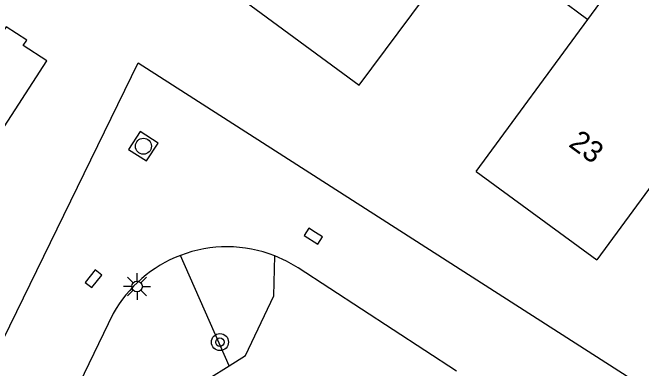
# Model space of a CAD drawing. Extents: x 136000 to 141000, y 400494 to 402006.
# Drawn here: x 137668.02 to 137697.45, y 401848.15 to 401864.81 of the extents above; entities that cross this region are included whole.
import ezdxf

# ---------------------------------------------------------------- set-up
doc = ezdxf.new("R2010")
doc.units = 0
for name, color, linetype in [('gg-anno-huisnummerreeks BGT', 7, 'Continuous'), ('gg-bbg-gedigitaliseerde bebouwing', 7, 'Continuous'), ('gg-bbg-hoofdgebouw', 7, 'Continuous'), ('gg-bbg-luifel en loopbrug', 7, 'Continuous'), ('gg-knt-verharding', 7, 'Continuous'), ('gt-grn-groengrens', 7, 'Continuous'), ('gt-symb-boom', 7, 'Continuous'), ('gt-symb-kolk', 7, 'Continuous'), ('gt-symb-lichtmast', 7, 'Continuous'), ('gt-symb-rioolschacht', 7, 'Continuous')]:
    doc.layers.add(name, color=color, linetype=linetype)

# ---------------------------------------------------------------- blocks, each defined once
blk = doc.blocks.new('gt0-KOLK')
at = {"layer": 'gt-symb-kolk'}
blk.add_lwpolyline([(0, 0), (0.375, 0), (0.375, 0.4), (-0.375, 0.4), (-0.375, 0), (0, 0)], dxfattribs=at)
blk = doc.blocks.new('gt0-BOOM')
at = {"layer": 'gt-symb-boom'}
for radius in [0.4, 0.2]:
    blk.add_circle((0, 0), radius, dxfattribs=at)
blk = doc.blocks.new('gt0-LMAST')
at = {"layer": 'gt-symb-lichtmast'}
for p, q in [((-0.005, 0.246), (-0.005, 0.621)), ((-0.182, 0.173), (-0.447, 0.438)), ((0.172, 0.173), (0.437, 0.438)), ((-0.255, -0.004), (-0.63, -0.004)), ((-0.182, -0.181), (-0.447, -0.446)), ((-0.005, -0.254), (-0.005, -0.629)), ((0.437, -0.446), (0.172, -0.181)), ((0.245, -0.004), (0.62, -0.004))]:
    blk.add_line(p, q, dxfattribs=at)
blk.add_circle((-0.005, -0.004), 0.25, dxfattribs=at)
blk = doc.blocks.new('gt0-RS')
at = {"layer": 'gt-symb-rioolschacht'}
blk.add_lwpolyline([(-0.5, -0.5), (0.5, -0.5), (0.5, 0.5), (-0.5, 0.5)], close=True, dxfattribs=at)
blk.add_circle((0, 0), 0.375, dxfattribs=at)

msp = doc.modelspace()

# ---------------------------------------------------------------- linework, layer by layer
at = {"layer": 'gg-bbg-gedigitaliseerde bebouwing'}
for p, q in [((137689.72, 401857.38), (137694.942, 401864.492)), ((137700.721, 401860.531), (137695.36, 401853.24))]:
    msp.add_line(p, q, dxfattribs=at)
for points in [[(137668.682, 401863.523), (137667.713, 401864.154), (137667.546, 401863.896), (137659.573, 401869.063), (137656.035, 401863.605)], [(137694.942, 401864.492), (137697.193, 401867.559), (137697.268, 401867.504)]]:
    msp.add_lwpolyline(points, dxfattribs=at)
at = {"layer": 'gg-bbg-hoofdgebouw'}
for p, q in [((137684.24, 401861.41), (137689.544, 401868.536)), ((137678.62, 401865.56), (137684.24, 401861.41)), ((137666.083, 401857.098), (137669.625, 401862.548)), ((137689.72, 401857.38), (137695.36, 401853.24))]:
    msp.add_line(p, q, dxfattribs=at)
msp.add_lwpolyline([(137669.625, 401862.548), (137668.516, 401863.267), (137668.682, 401863.523)], dxfattribs=at)
at = {"layer": 'gg-bbg-luifel en loopbrug'}
msp.add_line((137692.219, 401866.532), (137694.942, 401864.492), dxfattribs=at)
at = {"layer": 'gg-knt-verharding'}
msp.add_line((137672.731, 401850.723), (137670.497, 401846.143), dxfattribs=at)
for points in [[(137664.725, 401843.686), (137673.9, 401862.46), (137704.6, 401842.78)], [(137688.795, 401848.033), (137681.38, 401852.86), (137680.849, 401853.169), (137680.292, 401853.422)]]:
    msp.add_lwpolyline(points, dxfattribs=at)
for centre, radius, start, end in [((137678.053, 401847.751), 6.097, 68.4525, 110.8985), ((137678.056, 401847.751), 6.098, 110.9256, 150.8324)]:
    msp.add_arc(centre, radius, start, end, dxfattribs=at)
at = {"layer": 'gt-grn-groengrens'}
for p, q in [((137678.158, 401848.275), (137675.878, 401853.447)), ((137677.2, 401847.683), (137678.158, 401848.275))]:
    msp.add_line(p, q, dxfattribs=at)
msp.add_lwpolyline([(137678.158, 401848.275), (137678.93, 401848.752), (137680.253, 401851.551), (137680.292, 401853.422)], dxfattribs=at)

# ---------------------------------------------------------------- block references
at = {"layer": 'gt-symb-boom'}
msp.add_blockref('gt0-BOOM', (137677.727, 401849.387), dxfattribs=at)
at = {"layer": 'gt-symb-kolk'}
for p, rotation in [((137682.203, 401854.513), 147.45410660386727), ((137671.652, 401852.478), -128.01566048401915)]:
    msp.add_blockref('gt0-KOLK', p, dxfattribs=dict(at, rotation=rotation))
at = {"layer": 'gt-symb-lichtmast'}
msp.add_blockref('gt0-LMAST', (137673.85, 401851.992), dxfattribs=at)
at = {"layer": 'gt-symb-rioolschacht', "rotation": -32.673277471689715}
msp.add_blockref('gt0-RS', (137674.144, 401858.557), dxfattribs=at)

# ---------------------------------------------------------------- texts
at = {"layer": 'gg-anno-huisnummerreeks BGT'}
msp.add_text('23', height=1, rotation=323.7, dxfattribs=at).set_placement((137694, 401858.581))

doc.saveas('drawing.dxf')
